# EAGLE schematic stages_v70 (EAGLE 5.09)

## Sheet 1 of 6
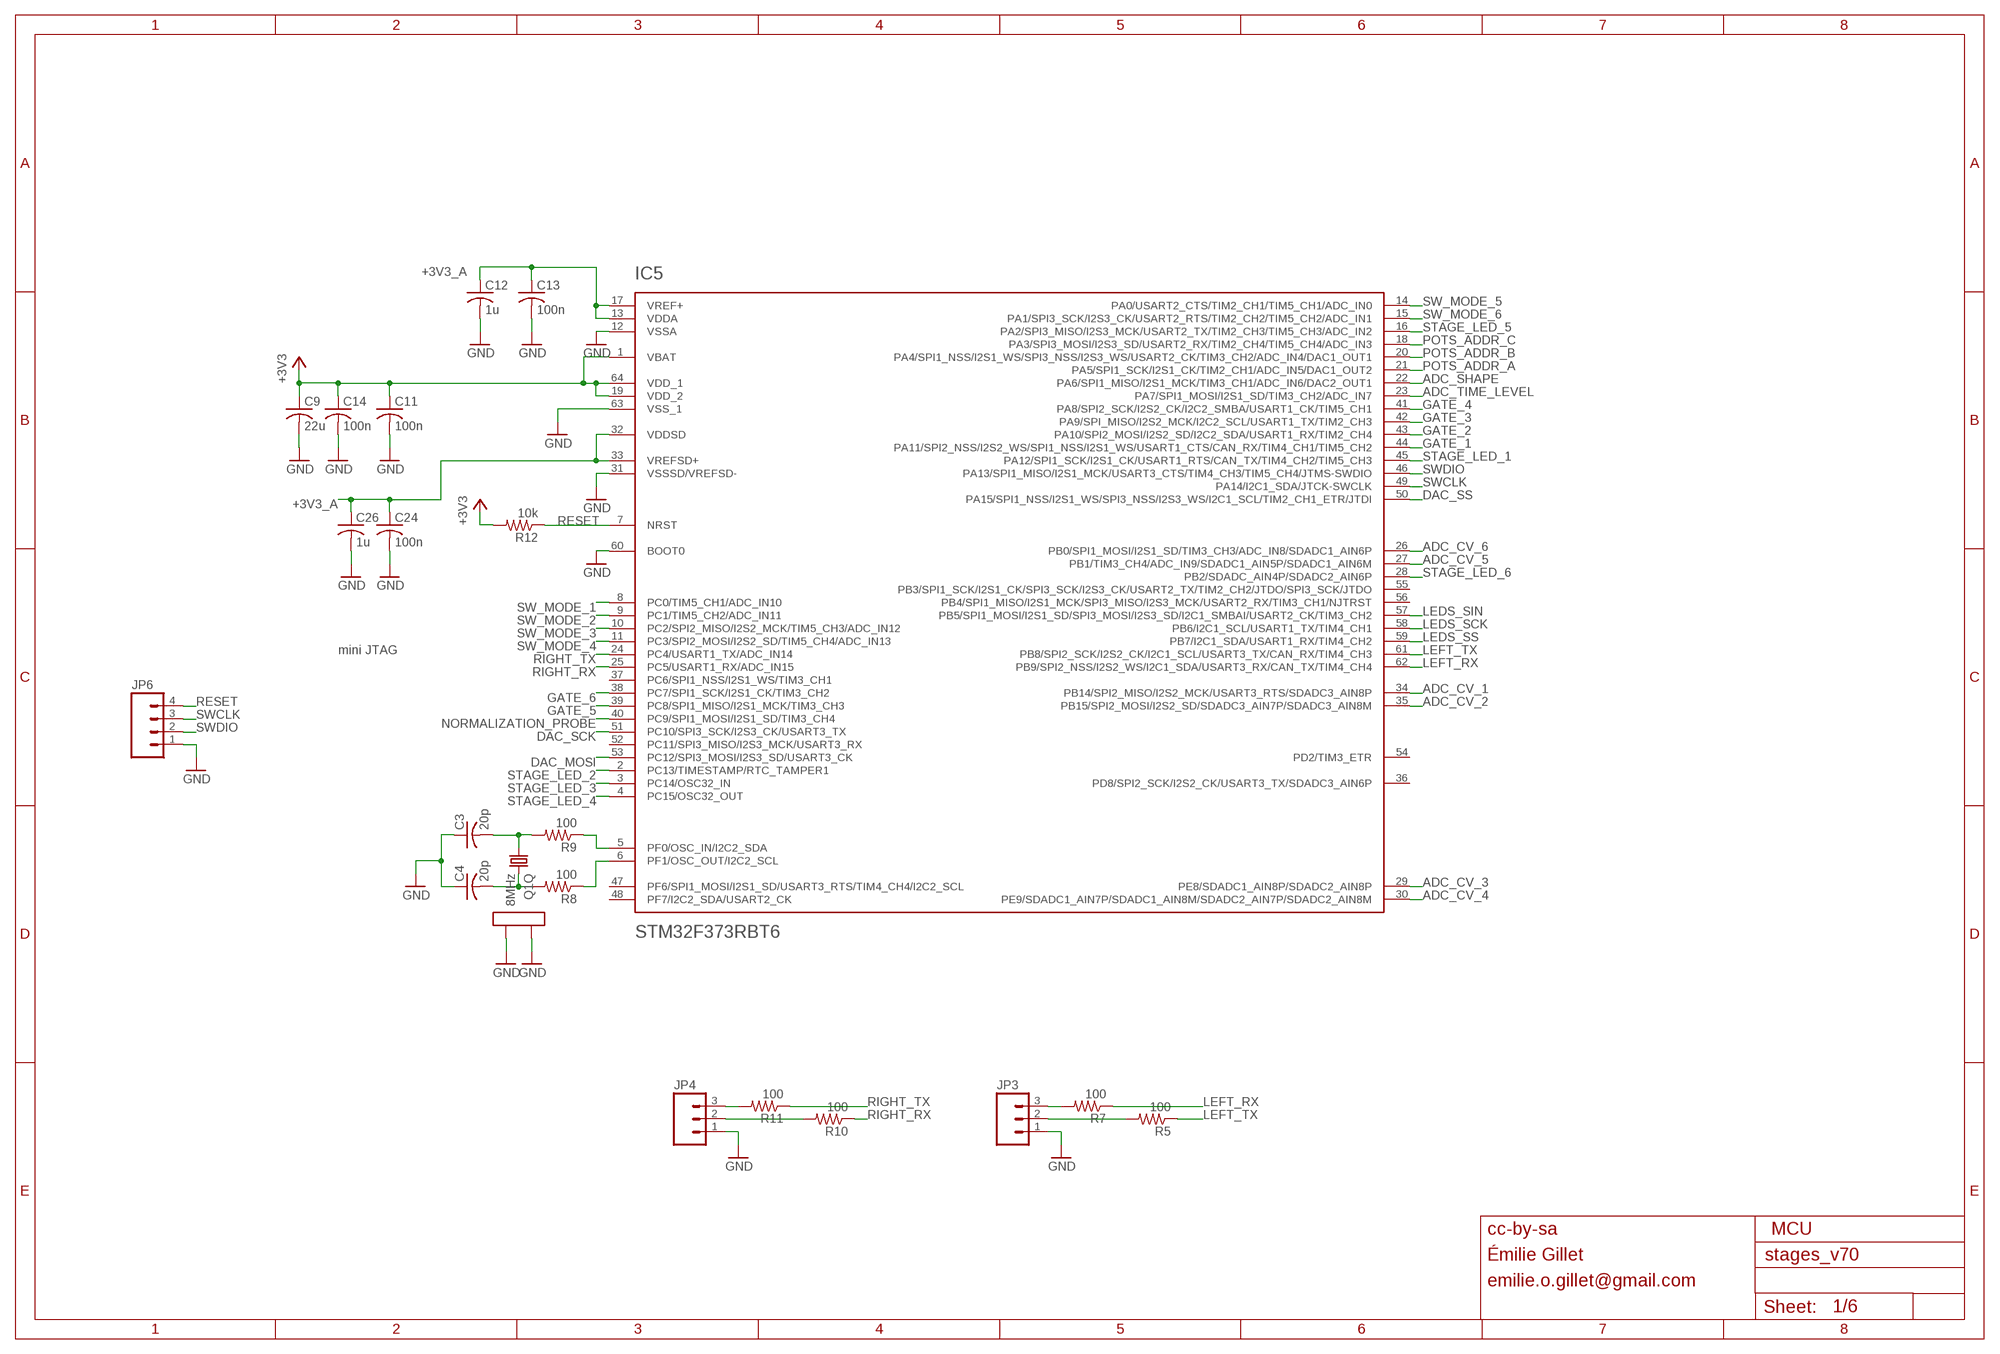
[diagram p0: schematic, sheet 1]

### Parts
C3  20p  C-USC0402  [C0402]
C4  20p  C-USC0402  [C0402]
C9  22u  C-USC1206  [C1206]
C11  100n  C-USC0402  [C0402]
C12  1u  C-USC0402  [C0402]
C13  100n  C-USC0402  [C0402]
C14  100n  C-USC0402  [C0402]
C24  100n  C-USC0402  [C0402]
C26  1u  C-USC0402  [C0402]
IC5  STM32F373RBT6  STM32F373R  [TQFP-10X10-64]
JP3  M03PTH  [1X03]
JP4  M03PTH  [1X03]
JP6  M04PTH  [1X04]
Q1  8MHz  CRYSTAL  [CTS406]
R5  100  R-US_R0402  [R0402]
R7  100  R-US_R0402  [R0402]
R8  100  R-US_R0402  [R0402]
R9  100  R-US_R0402  [R0402]
R10  100  R-US_R0402  [R0402]
R11  100  R-US_R0402  [R0402]
R12  10k  R-US_R0402  [R0402]

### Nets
+3V3: C9.1 C11.1 C14.1 IC5.1(VBAT) IC5.19(VDD_2) IC5.64(VDD_1) R12.2 ; also sheet 2,4,6
+3V3_A: C12.1 C13.1 C24.1 C26.1 IC5.13(VDDA) IC5.17(VREF+) IC5.32(VDDSD) IC5.33(VREFSD+) ; also sheet 2,3,5,6
ADC_CV_1: IC5.34(PB14/SPI2_MISO/I2S2_MCK/USART3_RTS/SDADC3_AIN8P) ; also sheet 3
ADC_CV_2: IC5.35(PB15/SPI2_MOSI/I2S2_SD/SDADC3_AIN7P/SDADC3_AIN8M) ; also sheet 3
ADC_CV_3: IC5.29(PE8/SDADC1_AIN8P/SDADC2_AIN8P) ; also sheet 3
ADC_CV_4: IC5.30(PE9/SDADC1_AIN7P/SDADC1_AIN8M/SDADC2_AIN7P/SDADC2_AIN8M) ; also sheet 3
ADC_CV_5: IC5.27(PB1/TIM3_CH4/ADC_IN9/SDADC1_AIN5P/SDADC1_AIN6M) ; also sheet 3
ADC_CV_6: IC5.26(PB0/SPI1_MOSI/I2S1_SD/TIM3_CH3/ADC_IN8/SDADC1_AIN6P) ; also sheet 3
ADC_SHAPE: IC5.22(PA6/SPI1_MISO/I2S1_MCK/TIM3_CH1/ADC_IN6/DAC2_OUT1) ; also sheet 2
ADC_TIME_LEVEL: IC5.23(PA7/SPI1_MOSI/I2S1_SD/TIM3_CH2/ADC_IN7) ; also sheet 2
DAC_MOSI: IC5.53(PC12/SPI3_MOSI/I2S3_SD/USART3_CK) ; also sheet 5
DAC_SCK: IC5.51(PC10/SPI3_SCK/I2S3_CK/USART3_TX) ; also sheet 5
DAC_SS: IC5.50(PA15/SPI1_NSS/I2S1_WS/SPI3_NSS/I2S3_WS/I2C1_SCL/TIM2_CH1_ETR/JTDI) ; also sheet 5
GATE_1: IC5.44(PA11/SPI2_NSS/I2S2_WS/SPI1_NSS/I2S1_WS/USART1_CTS/CAN_RX/TIM4_CH1/TIM5_CH2) ; also sheet 4
GATE_2: IC5.43(PA10/SPI2_MOSI/I2S2_SD/I2C2_SDA/USART1_RX/TIM2_CH4) ; also sheet 4
GATE_3: IC5.42(PA9/SPI_MISO/I2S2_MCK/I2C2_SCL/USART1_TX/TIM2_CH3) ; also sheet 4
GATE_4: IC5.41(PA8/SPI2_SCK/I2S2_CK/I2C2_SMBA/USART1_CK/TIM5_CH1) ; also sheet 4
GATE_5: IC5.39(PC8/SPI1_MISO/I2S1_MCK/TIM3_CH3) ; also sheet 4
GATE_6: IC5.38(PC7/SPI1_SCK/I2S1_CK/TIM3_CH2) ; also sheet 4
GND: C3.1 C4.1 C9.2 C11.2 C12.2 C13.2 C14.2 C24.2 C26.2 IC5.12(VSSA) IC5.31(VSSSD/VREFSD-) IC5.60(BOOT0) IC5.63(VSS_1) JP3.1 JP4.1 JP6.1 Q1.2(LID1) Q1.4(LID2) ; also sheet 2,3,4,5,6
LEDS_SCK: IC5.58(PB6/I2C1_SCL/USART1_TX/TIM4_CH1) ; also sheet 2
LEDS_SIN: IC5.57(PB5/SPI1_MOSI/I2S1_SD/SPI3_MOSI/I2S3_SD/I2C1_SMBAI/USART2_CK/TIM3_CH2) ; also sheet 2
LEDS_SS: IC5.59(PB7/I2C1_SDA/USART1_RX/TIM4_CH2) ; also sheet 2
LEFT_RX: IC5.62(PB9/SPI2_NSS/I2S2_WS/I2C1_SDA/USART3_RX/CAN_TX/TIM4_CH4) R7.1
LEFT_RX_R: JP3.3 R7.2
LEFT_TX: IC5.61(PB8/SPI2_SCK/I2S2_CK/I2C1_SCL/USART3_TX/CAN_RX/TIM4_CH3) R5.1
LEFT_TX_R: JP3.2 R5.2
N$7: C3.2 Q1.1 R9.2
N$8: C4.2 Q1.3 R8.2
N$15: IC5.5(PF0/OSC_IN/I2C2_SDA) R9.1
N$29: IC5.6(PF1/OSC_OUT/I2C2_SCL) R8.1
NORMALIZATION_PROBE: IC5.40(PC9/SPI1_MOSI/I2S1_SD/TIM3_CH4) ; also sheet 4
POTS_ADDR_A: IC5.21(PA5/SPI1_SCK/I2S1_CK/TIM2_CH1/ADC_IN5/DAC1_OUT2) ; also sheet 2
POTS_ADDR_B: IC5.20(PA4/SPI1_NSS/I2S1_WS/SPI3_NSS/I2S3_WS/USART2_CK/TIM3_CH2/ADC_IN4/DAC1_OUT1) ; also sheet 2
POTS_ADDR_C: IC5.18(PA3/SPI3_MOSI/I2S3_SD/USART2_RX/TIM2_CH4/TIM5_CH4/ADC_IN3) ; also sheet 2
RESET: IC5.7(NRST) JP6.4 R12.1
RIGHT_RX: IC5.25(PC5/USART1_RX/ADC_IN15) R10.1
RIGHT_RX_R: JP4.2 R10.2
RIGHT_TX: IC5.24(PC4/USART1_TX/ADC_IN14) R11.1
RIGHT_TX_R: JP4.3 R11.2
STAGE_LED_1: IC5.45(PA12/SPI1_SCK/I2S1_CK/USART1_RTS/CAN_TX/TIM4_CH2/TIM5_CH3) ; also sheet 2
STAGE_LED_2: IC5.2(PC13/TIMESTAMP/RTC_TAMPER1) ; also sheet 2
STAGE_LED_3: IC5.3(PC14/OSC32_IN) ; also sheet 2
STAGE_LED_4: IC5.4(PC15/OSC32_OUT) ; also sheet 2
STAGE_LED_5: IC5.16(PA2/SPI3_MISO/I2S3_MCK/USART2_TX/TIM2_CH3/TIM5_CH3/ADC_IN2) ; also sheet 2
STAGE_LED_6: IC5.28(PB2/SDADC_AIN4P/SDADC2_AIN6P) ; also sheet 2
SW_MODE_1: IC5.8(PC0/TIM5_CH1/ADC_IN10) ; also sheet 2
SW_MODE_2: IC5.9(PC1/TIM5_CH2/ADC_IN11) ; also sheet 2
SW_MODE_3: IC5.10(PC2/SPI2_MISO/I2S2_MCK/TIM5_CH3/ADC_IN12) ; also sheet 2
SW_MODE_4: IC5.11(PC3/SPI2_MOSI/I2S2_SD/TIM5_CH4/ADC_IN13) ; also sheet 2
SW_MODE_5: IC5.14(PA0/USART2_CTS/TIM2_CH1/TIM5_CH1/ADC_IN0) ; also sheet 2
SW_MODE_6: IC5.15(PA1/SPI3_SCK/I2S3_CK/USART2_RTS/TIM2_CH2/TIM5_CH2/ADC_IN1) ; also sheet 2
SWCLK: IC5.49(PA14/I2C1_SDA/JTCK-SWCLK) JP6.3
SWDIO: IC5.46(PA13/SPI1_MISO/I2S1_MCK/USART3_CTS/TIM4_CH3/TIM5_CH4/JTMS-SWDIO) JP6.2
Unconnected: IC5.36(PD8/SPI2_SCK/I2S2_CK/USART3_TX/SDADC3_AIN6P) IC5.37(PC6/SPI1_NSS/I2S1_WS/TIM3_CH1) IC5.47(PF6/SPI1_MOSI/I2S1_SD/USART3_RTS/TIM4_CH4/I2C2_SCL) IC5.48(PF7/I2C2_SDA/USART2_CK) IC5.52(PC11/SPI3_MISO/I2S3_MCK/USART3_RX) IC5.54(PD2/TIM3_ETR) IC5.55(PB3/SPI1_SCK/I2S1_CK/SPI3_SCK/I2S3_CK/USART2_TX/TIM2_CH2/JTDO/SPI3_SCK/JTDO) IC5.56(PB4/SPI1_MISO/I2S1_MCK/SPI3_MISO/I2S3_MCK/USART2_RX/TIM3_CH1/NJTRST)

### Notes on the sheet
- mini JTAG
- cc-by-sa | MCU
- Émilie Gillet
- emilie.o.gillet@gmail.com

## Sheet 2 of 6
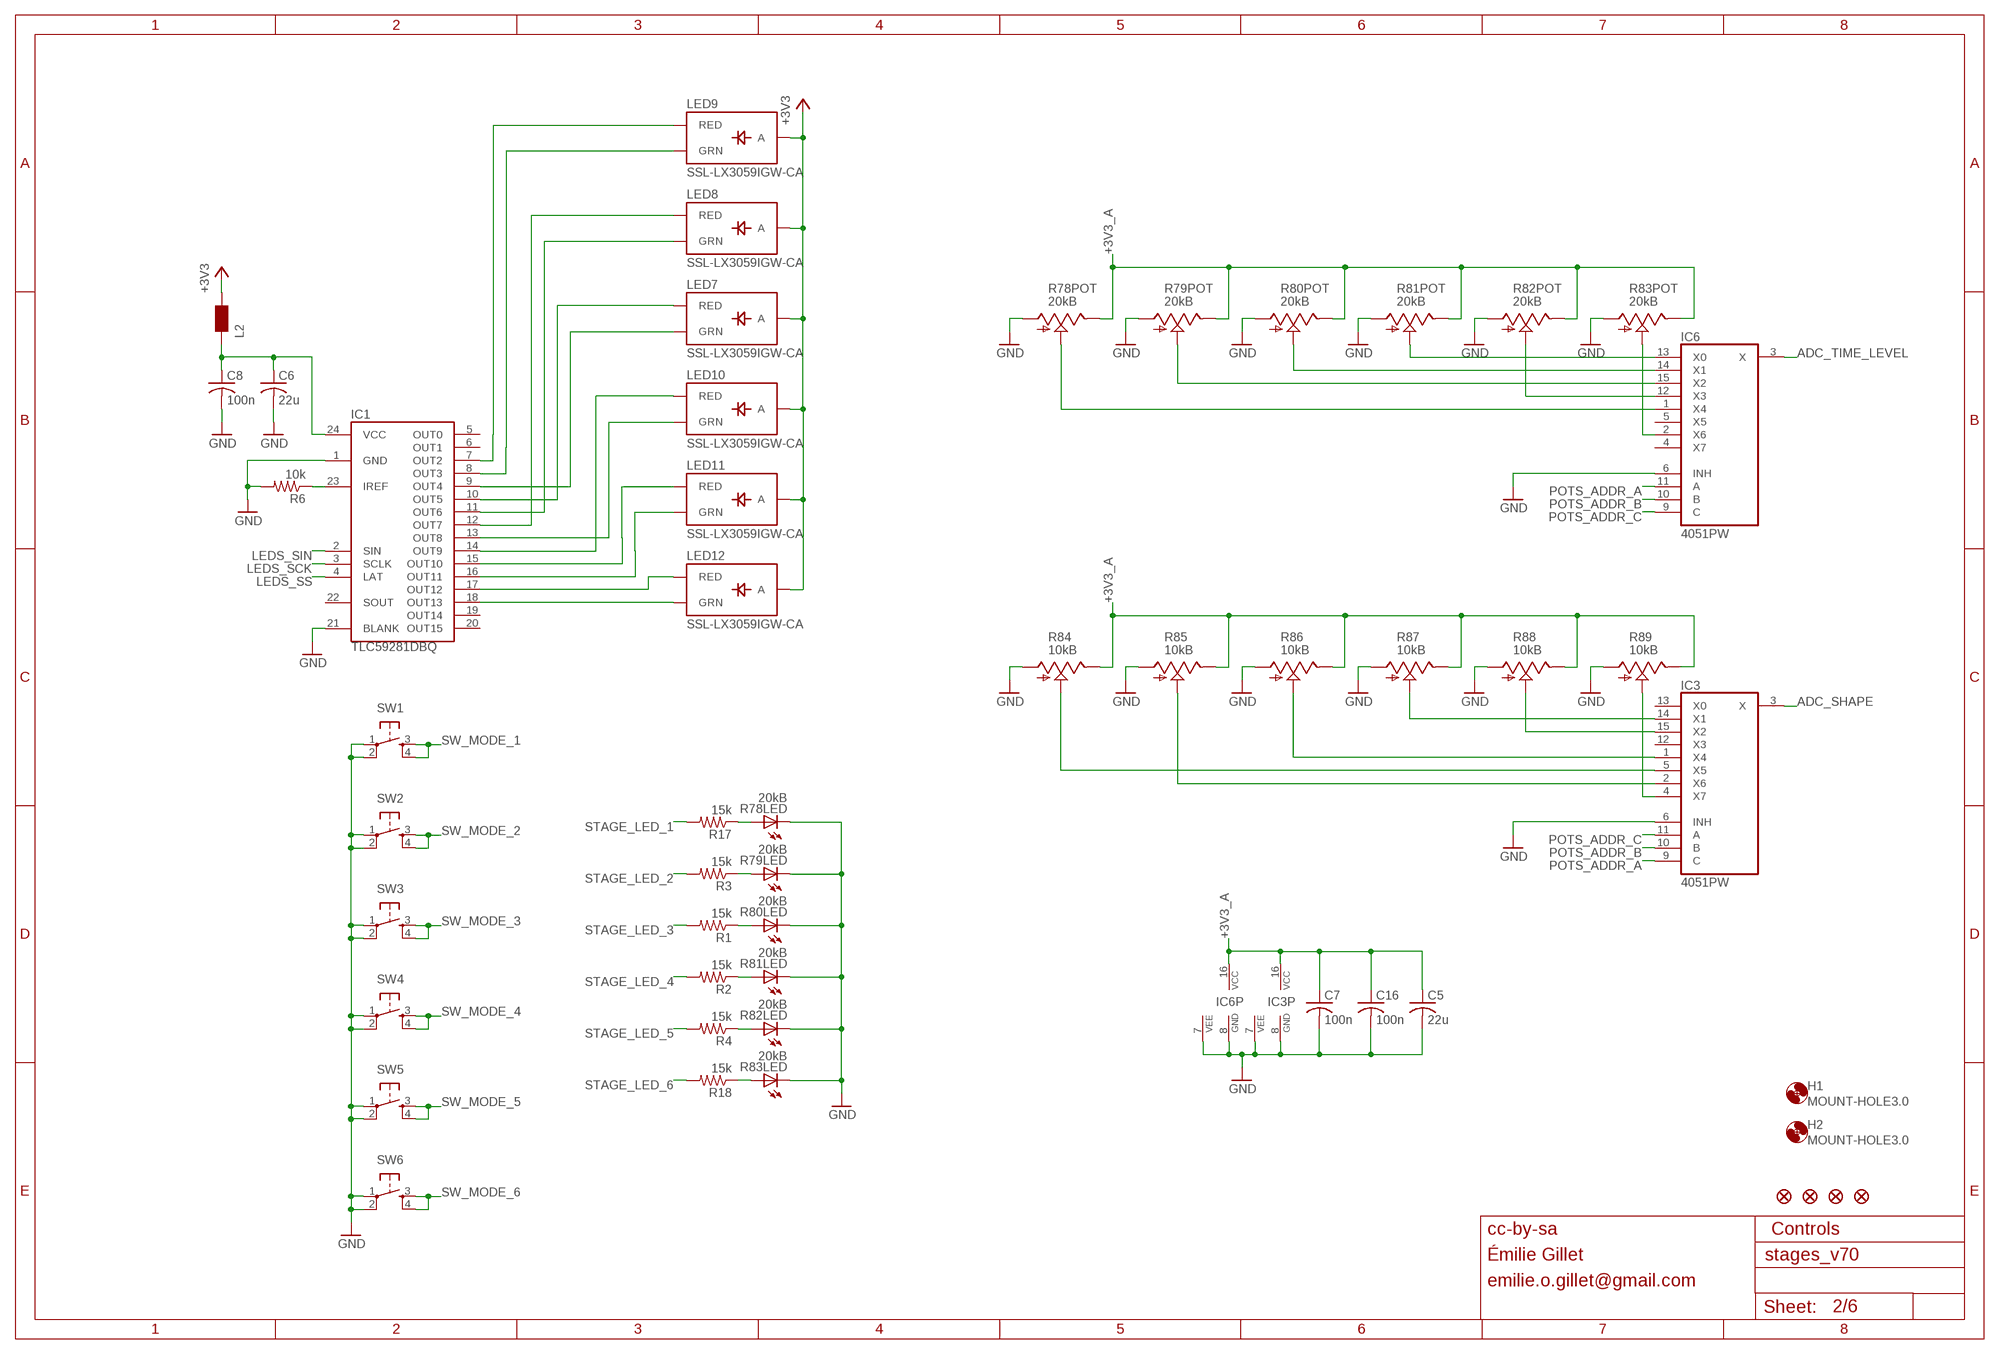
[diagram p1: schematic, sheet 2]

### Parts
C5  22u  C-USC1206  [C1206]
C6  22u  C-USC1206  [C1206]
C7  100n  C-USC0402  [C0402]
C8  100n  C-USC0402  [C0402]
C16  100n  C-USC0402  [C0402]
H1  MOUNT-HOLE3.0  [3,0]
H2  MOUNT-HOLE3.0  [3,0]
IC1  TLC59281DBQ  [TSSOP24_0635]
IC3  4051PW  [TSSOP16_065]
IC6  4051PW  [TSSOP16_065]
JP1  FIDUCIAL1X2  [FIDUCIAL-1X2]
JP2  FIDUCIAL1X2  [FIDUCIAL-1X2]
JP7  FIDUCIAL1X2  [FIDUCIAL-1X2]
JP8  FIDUCIAL1X2  [FIDUCIAL-1X2]
L2  WE-CBF_0603  [0603]
LED7  SSL-LX3059IGW-CA  LED-BICOLOR-THROUGHHOLE-CA  [LED-BICOLOR-THROUGHHOLE-LUMEX]
LED8  SSL-LX3059IGW-CA  LED-BICOLOR-THROUGHHOLE-CA  [LED-BICOLOR-THROUGHHOLE-LUMEX]
LED9  SSL-LX3059IGW-CA  LED-BICOLOR-THROUGHHOLE-CA  [LED-BICOLOR-THROUGHHOLE-LUMEX]
LED10  SSL-LX3059IGW-CA  LED-BICOLOR-THROUGHHOLE-CA  [LED-BICOLOR-THROUGHHOLE-LUMEX]
LED11  SSL-LX3059IGW-CA  LED-BICOLOR-THROUGHHOLE-CA  [LED-BICOLOR-THROUGHHOLE-LUMEX]
LED12  SSL-LX3059IGW-CA  LED-BICOLOR-THROUGHHOLE-CA  [LED-BICOLOR-THROUGHHOLE-LUMEX]
R1  15k  R-US_R0402  [R0402]
R2  15k  R-US_R0402  [R0402]
R3  15k  R-US_R0402  [R0402]
R4  15k  R-US_R0402  [R0402]
R6  10k  R-US_R0402  [R0402]
R17  15k  R-US_R0402  [R0402]
R18  15k  R-US_R0402  [R0402]
R78  20kB  BOURNS_SLIDER  [BOURNS_SLIDER]
R79  20kB  BOURNS_SLIDER  [BOURNS_SLIDER]
R80  20kB  BOURNS_SLIDER  [BOURNS_SLIDER]
R81  20kB  BOURNS_SLIDER  [BOURNS_SLIDER]
R82  20kB  BOURNS_SLIDER  [BOURNS_SLIDER]
R83  20kB  BOURNS_SLIDER  [BOURNS_SLIDER]
R84  10kB  POT_USVERTICAL_NARROW  [ALPS_POT_NARROW]
R85  10kB  POT_USVERTICAL_NARROW  [ALPS_POT_NARROW]
R86  10kB  POT_USVERTICAL_NARROW  [ALPS_POT_NARROW]
R87  10kB  POT_USVERTICAL_NARROW  [ALPS_POT_NARROW]
R88  10kB  POT_USVERTICAL_NARROW  [ALPS_POT_NARROW]
R89  10kB  POT_USVERTICAL_NARROW  [ALPS_POT_NARROW]
SW1  TAC_SWITCHPTH  [TACTILE-PTH]
SW2  TAC_SWITCHPTH  [TACTILE-PTH]
SW3  TAC_SWITCHPTH  [TACTILE-PTH]
SW4  TAC_SWITCHPTH  [TACTILE-PTH]
SW5  TAC_SWITCHPTH  [TACTILE-PTH]
SW6  TAC_SWITCHPTH  [TACTILE-PTH]

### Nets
+3V3: L2.2 LED7.A LED8.A LED9.A LED10.A LED11.A LED12.A ; also sheet 1,4,6
+3V3_A: C5.1 C7.1 C16.1 IC3.16(VCC) IC6.16(VCC) R78.3(POT:E) R79.3(POT:E) R80.3(POT:E) R81.3(POT:E) R82.3(POT:E) R83.3(POT:E) R84.P$1(E) R85.P$1(E) R86.P$1(E) R87.P$1(E) R88.P$1(E) R89.P$1(E) ; also sheet 1,3,5,6
ADC_SHAPE: IC3.3(X) ; also sheet 1
ADC_TIME_LEVEL: IC6.3(X) ; also sheet 1
GND: C5.2 C6.2 C7.2 C8.2 C16.2 IC1.1(GND) IC1.21(BLANK) IC3.6(INH) IC3.7(VEE) IC3.8(GND) IC6.6(INH) IC6.7(VEE) IC6.8(GND) R6.2 R78.1(POT:A) R78.E(LED:C) R79.1(POT:A) R79.E(LED:C) R80.1(POT:A) R80.E(LED:C) R81.1(POT:A) R81.E(LED:C) R82.1(POT:A) R82.E(LED:C) R83.1(POT:A) R83.E(LED:C) R84.P$3(A) R85.P$3(A) R86.P$3(A) R87.P$3(A) R88.P$3(A) R89.P$3(A) SW1.1 SW1.2 SW2.1 SW2.2 SW3.1 SW3.2 SW4.1 SW4.2 SW5.1 SW5.2 SW6.1 SW6.2 ; also sheet 1,3,4,5,6
LEDS_SCK: IC1.3(SCLK) ; also sheet 1
LEDS_SIN: IC1.2(SIN) ; also sheet 1
LEDS_SS: IC1.4(LAT) ; also sheet 1
N$2: IC1.10(OUT5) LED7.RED_C(RED)
N$3: IC1.18(OUT13) LED12.GREEN_C(GRN)
N$4: IC1.12(OUT7) LED8.RED_C(RED)
N$6: IC1.7(OUT2) LED9.RED_C(RED)
N$9: IC1.8(OUT3) LED9.GREEN_C(GRN)
N$10: IC1.13(OUT8) LED10.GREEN_C(GRN)
N$12: IC1.15(OUT10) LED11.RED_C(RED)
N$13: R17.1 R78.B(LED:A)
N$14: IC1.16(OUT11) LED11.GREEN_C(GRN)
N$16: IC1.17(OUT12) LED12.RED_C(RED)
N$22: IC1.11(OUT6) LED8.GREEN_C(GRN)
N$31: C6.1 C8.1 IC1.24(VCC) L2.1
N$43: IC1.14(OUT9) LED10.RED_C(RED)
N$48: IC6.1(X4) R78.2(POT:S)
N$49: R18.1 R83.B(LED:A)
N$51: IC6.2(X6) R83.2(POT:S)
N$53: IC6.12(X3) R82.2(POT:S)
N$54: IC6.13(X0) R81.2(POT:S)
N$55: IC6.14(X1) R80.2(POT:S)
N$56: IC6.15(X2) R79.2(POT:S)
N$58: IC3.2(X6) R85.P$2(S)
N$59: IC3.4(X7) R89.P$2(S)
N$60: IC3.1(X4) R86.P$2(S)
N$61: IC3.14(X1) R87.P$2(S)
N$62: IC3.15(X2) R88.P$2(S)
N$63: IC3.5(X5) R84.P$2(S)
N$64: R4.1 R82.B(LED:A)
N$68: IC1.23(IREF) R6.1
N$100: R2.1 R81.B(LED:A)
N$101: IC1.9(OUT4) LED7.GREEN_C(GRN)
N$102: R1.1 R80.B(LED:A)
N$103: R3.1 R79.B(LED:A)
POTS_ADDR_A: IC3.9(C) IC6.11(A) ; also sheet 1
POTS_ADDR_B: IC3.10(B) IC6.10(B) ; also sheet 1
POTS_ADDR_C: IC3.11(A) IC6.9(C) ; also sheet 1
STAGE_LED_1: R17.2 ; also sheet 1
STAGE_LED_2: R3.2 ; also sheet 1
STAGE_LED_3: R1.2 ; also sheet 1
STAGE_LED_4: R2.2 ; also sheet 1
STAGE_LED_5: R4.2 ; also sheet 1
STAGE_LED_6: R18.2 ; also sheet 1
SW_MODE_1: SW1.3 SW1.4 ; also sheet 1
SW_MODE_2: SW2.3 SW2.4 ; also sheet 1
SW_MODE_3: SW3.3 SW3.4 ; also sheet 1
SW_MODE_4: SW4.3 SW4.4 ; also sheet 1
SW_MODE_5: SW5.3 SW5.4 ; also sheet 1
SW_MODE_6: SW6.3 SW6.4 ; also sheet 1
Unconnected: IC1.5(OUT0) IC1.6(OUT1) IC1.19(OUT14) IC1.20(OUT15) IC1.22(SOUT) IC3.12(X3) IC3.13(X0) IC6.4(X7) IC6.5(X5)

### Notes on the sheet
- cc-by-sa | Controls
- Émilie Gillet
- emilie.o.gillet@gmail.com

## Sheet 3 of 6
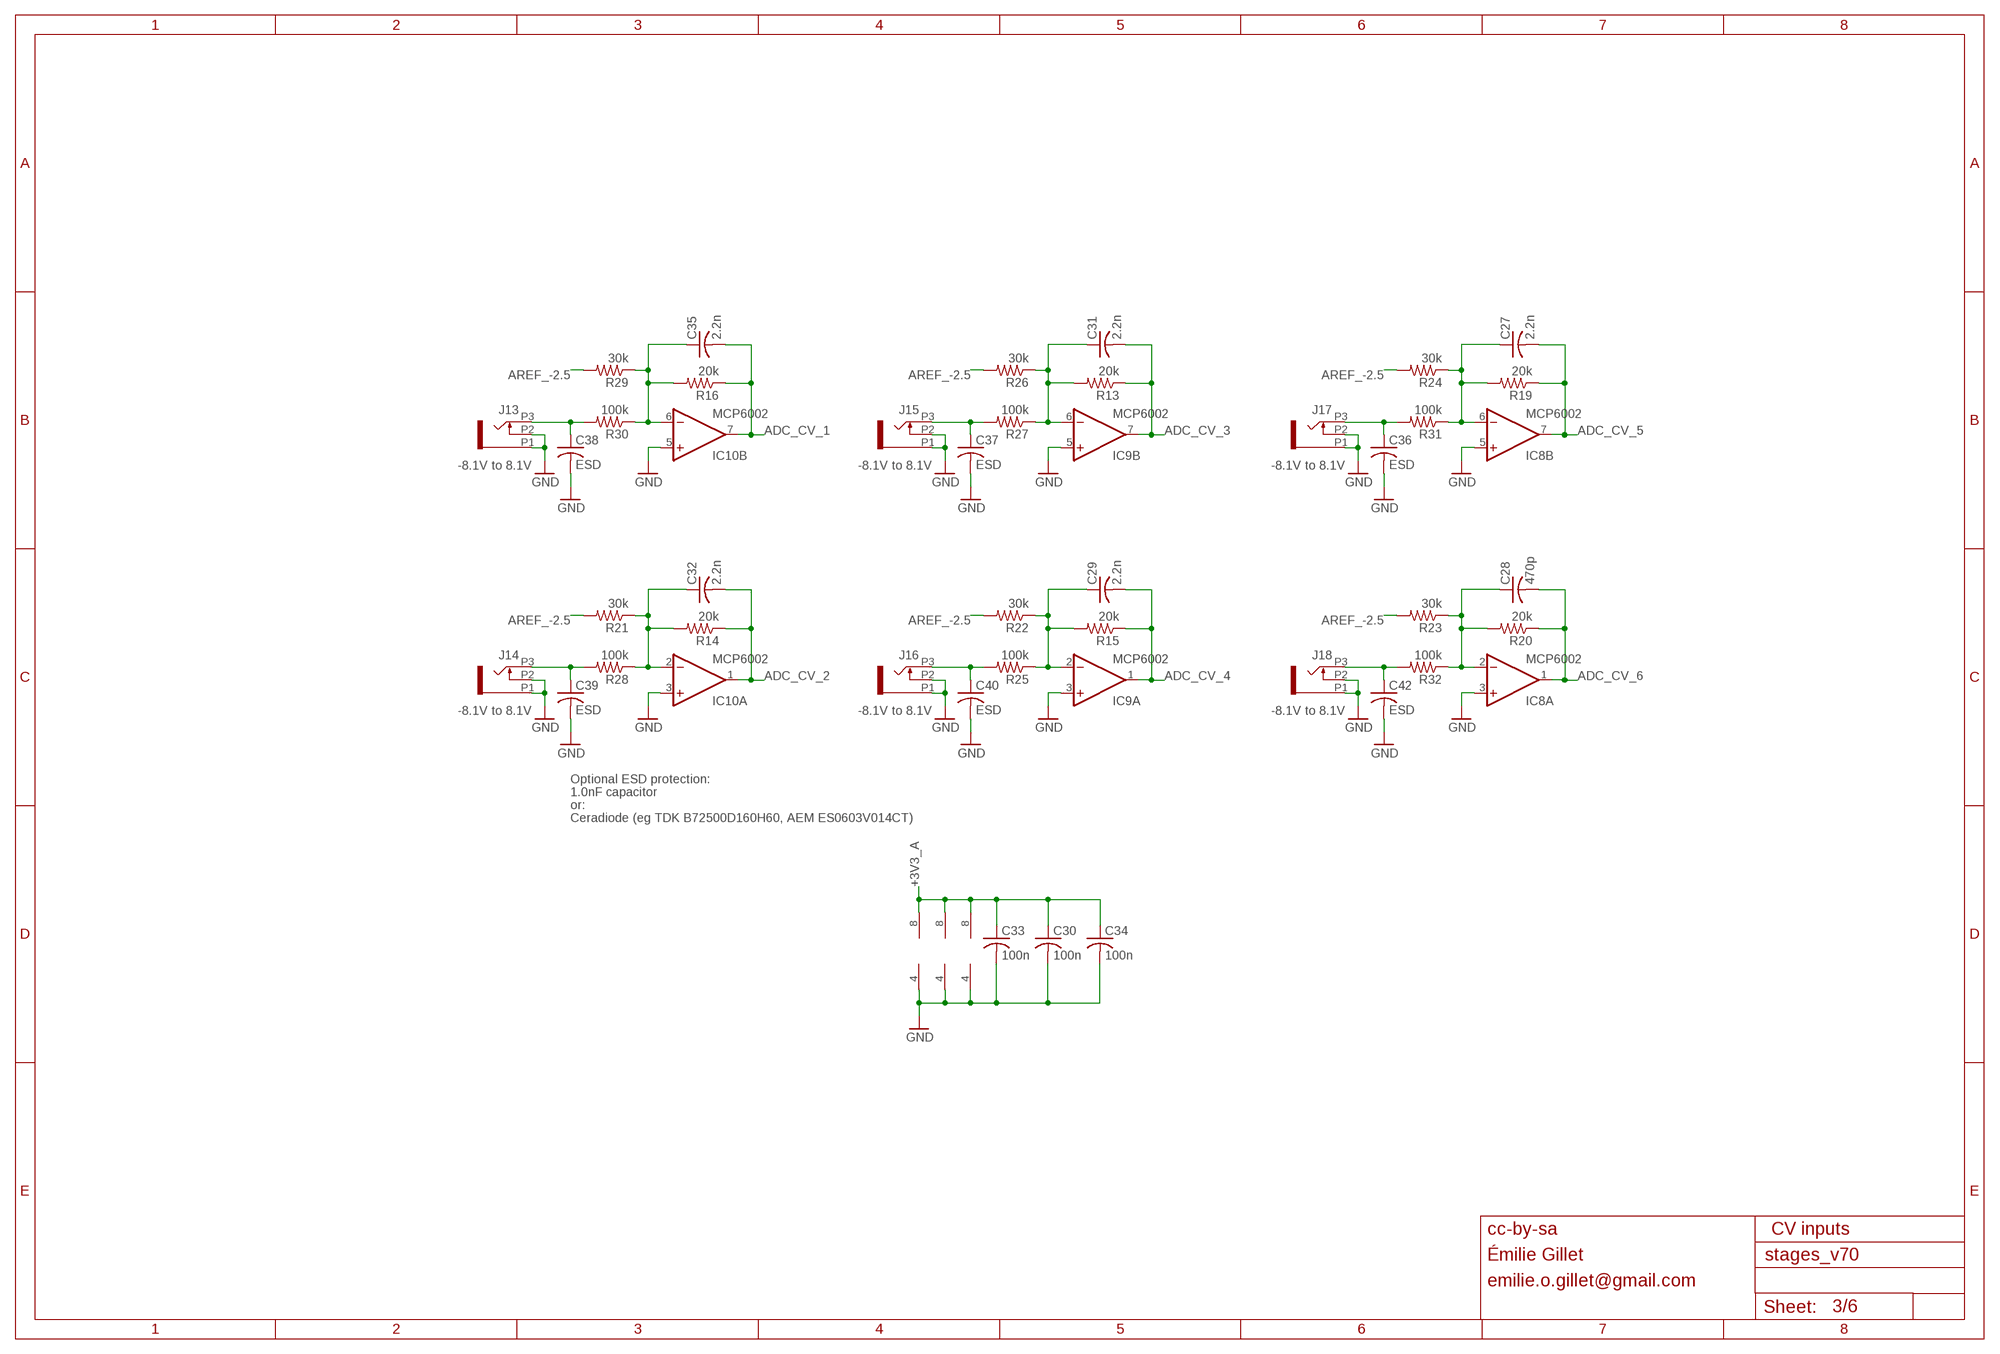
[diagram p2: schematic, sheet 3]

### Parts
C27  2.2n  C-USC0402  [C0402]
C28  470p  C-USC0402  [C0402]
C29  2.2n  C-USC0402  [C0402]
C30  100n  C-USC0402  [C0402]
C31  2.2n  C-USC0402  [C0402]
C32  2.2n  C-USC0402  [C0402]
C33  100n  C-USC0402  [C0402]
C34  100n  C-USC0402  [C0402]
C35  2.2n  C-USC0402  [C0402]
C36  ESD  C-USC0603  [C0603]
C37  ESD  C-USC0603  [C0603]
C38  ESD  C-USC0603  [C0603]
C39  ESD  C-USC0603  [C0603]
C40  ESD  C-USC0603  [C0603]
C42  ESD  C-USC0603  [C0603]
IC8  MCP6002  OPA1652DGK  [MSOP-8]
IC9  MCP6002  OPA1652DGK  [MSOP-8]
IC10  MCP6002  OPA1652DGK  [MSOP-8]
J13  PJ301_THONKICONN6  [WQP_PJ_301M6]
J14  PJ301_THONKICONN6  [WQP_PJ_301M6]
J15  PJ301_THONKICONN6  [WQP_PJ_301M6]
J16  PJ301_THONKICONN6  [WQP_PJ_301M6]
J17  PJ301_THONKICONN6  [WQP_PJ_301M6]
J18  PJ301_THONKICONN6  [WQP_PJ_301M6]
R13  20k  R-US_R0402  [R0402]
R14  20k  R-US_R0402  [R0402]
R15  20k  R-US_R0402  [R0402]
R16  20k  R-US_R0402  [R0402]
R19  20k  R-US_R0402  [R0402]
R20  20k  R-US_R0402  [R0402]
R21  30k  R-US_R0402  [R0402]
R22  30k  R-US_R0402  [R0402]
R23  30k  R-US_R0402  [R0402]
R24  30k  R-US_R0402  [R0402]
R25  100k  R-US_R0402  [R0402]
R26  30k  R-US_R0402  [R0402]
R27  100k  R-US_R0402  [R0402]
R28  100k  R-US_R0402  [R0402]
R29  30k  R-US_R0402  [R0402]
R30  100k  R-US_R0402  [R0402]
R31  100k  R-US_R0402  [R0402]
R32  100k  R-US_R0402  [R0402]

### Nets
+3V3_A: C30.1 C33.1 C34.1 IC8.8(P:V+) IC9.8(P:V+) IC10.8(P:V+) ; also sheet 1,2,5,6
ADC_CV_1: C35.2 IC10.7(B:OUT) R16.1 ; also sheet 1
ADC_CV_2: C32.2 IC10.1(A:OUT) R14.1 ; also sheet 1
ADC_CV_3: C31.2 IC9.7(B:OUT) R13.1 ; also sheet 1
ADC_CV_4: C29.2 IC9.1(A:OUT) R15.1 ; also sheet 1
ADC_CV_5: C27.2 IC8.7(B:OUT) R19.1 ; also sheet 1
ADC_CV_6: C28.2 IC8.1(A:OUT) R20.1 ; also sheet 1
AREF_-2.5: R21.2 R22.2 R23.2 R24.2 R26.2 R29.2 ; also sheet 6
GND: C30.2 C33.2 C34.2 C36.2 C37.2 C38.2 C39.2 C40.2 C42.2 IC8.3(A:+IN) IC8.4(P:V-) IC8.5(B:+IN) IC9.3(A:+IN) IC9.4(P:V-) IC9.5(B:+IN) IC10.3(A:+IN) IC10.4(P:V-) IC10.5(B:+IN) J13.P1 J13.P2 J14.P1 J14.P2 J15.P1 J15.P2 J16.P1 J16.P2 J17.P1 J17.P2 J18.P1 J18.P2 ; also sheet 1,2,4,5,6
MORPH_IN: C38.1 J13.P3 R30.2
MORPH_IN1: C39.1 J14.P3 R28.2
MORPH_IN2: C37.1 J15.P3 R27.2
MORPH_IN3: C40.1 J16.P3 R25.2
MORPH_IN4: C36.1 J17.P3 R31.2
MORPH_IN5: C42.1 J18.P3 R32.2
N$30: C35.1 IC10.6(B:-IN) R16.2 R29.1 R30.1
N$32: C32.1 IC10.2(A:-IN) R14.2 R21.1 R28.1
N$34: C31.1 IC9.6(B:-IN) R13.2 R26.1 R27.1
N$37: C29.1 IC9.2(A:-IN) R15.2 R22.1 R25.1
N$39: C27.1 IC8.6(B:-IN) R19.2 R24.1 R31.1
N$41: C28.1 IC8.2(A:-IN) R20.2 R23.1 R32.1

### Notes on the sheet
- -8.1V to 8.1V | -8.1V to 8.1V | -8.1V to 8.1V
- -8.1V to 8.1V | -8.1V to 8.1V | -8.1V to 8.1V
- Optional ESD protection:
- 1.0nF capacitor
- or:
- Ceradiode (eg TDK B72500D160H60, AEM ES0603V014CT)
- cc-by-sa | CV inputs
- Émilie Gillet
- emilie.o.gillet@gmail.com

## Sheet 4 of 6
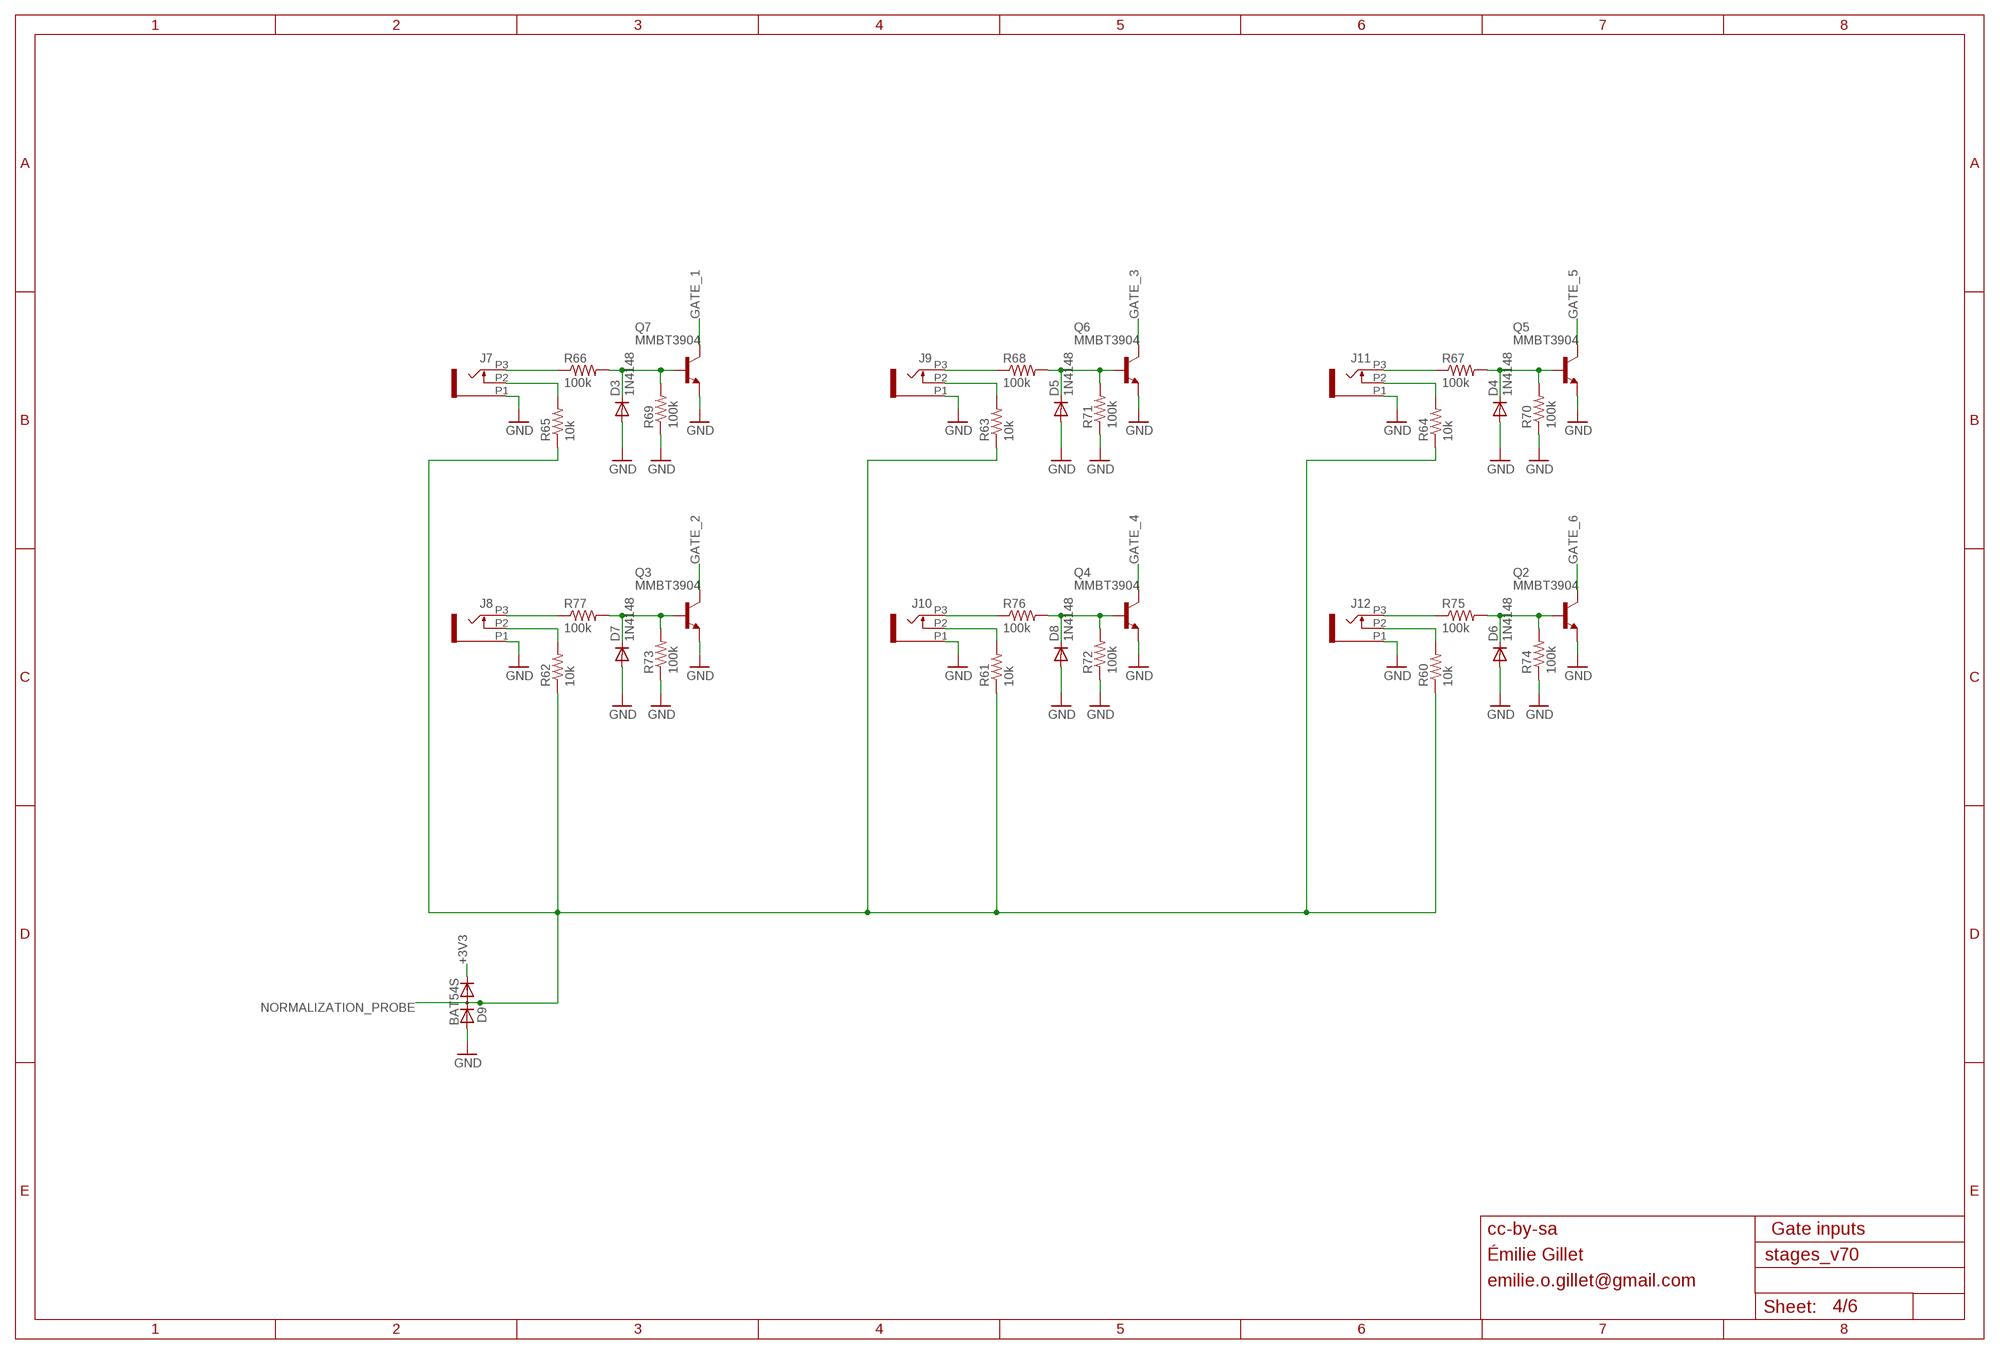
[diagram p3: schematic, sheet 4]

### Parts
D3  1N4148  DIODE-SOD523  [SOD523]
D4  1N4148  DIODE-SOD523  [SOD523]
D5  1N4148  DIODE-SOD523  [SOD523]
D6  1N4148  DIODE-SOD523  [SOD523]
D7  1N4148  DIODE-SOD523  [SOD523]
D8  1N4148  DIODE-SOD523  [SOD523]
D9  BAT54S  DIODE_2CACA-SOT23  [SOT23]
J7  PJ301_THONKICONN6  [WQP_PJ_301M6]
J8  PJ301_THONKICONN6  [WQP_PJ_301M6]
J9  PJ301_THONKICONN6  [WQP_PJ_301M6]
J10  PJ301_THONKICONN6  [WQP_PJ_301M6]
J11  PJ301_THONKICONN6  [WQP_PJ_301M6]
J12  PJ301_THONKICONN6  [WQP_PJ_301M6]
Q2  MMBT3904  MMBT3904LT1-NPN-SOT23-BEC  [SOT23-BEC]
Q3  MMBT3904  MMBT3904LT1-NPN-SOT23-BEC  [SOT23-BEC]
Q4  MMBT3904  MMBT3904LT1-NPN-SOT23-BEC  [SOT23-BEC]
Q5  MMBT3904  MMBT3904LT1-NPN-SOT23-BEC  [SOT23-BEC]
Q6  MMBT3904  MMBT3904LT1-NPN-SOT23-BEC  [SOT23-BEC]
Q7  MMBT3904  MMBT3904LT1-NPN-SOT23-BEC  [SOT23-BEC]
R60  10k  R-US_R0402  [R0402]
R61  10k  R-US_R0402  [R0402]
R62  10k  R-US_R0402  [R0402]
R63  10k  R-US_R0402  [R0402]
R64  10k  R-US_R0402  [R0402]
R65  10k  R-US_R0402  [R0402]
R66  100k  R-US_R0402  [R0402]
R67  100k  R-US_R0402  [R0402]
R68  100k  R-US_R0402  [R0402]
R69  100k  R-US_R0402  [R0402]
R70  100k  R-US_R0402  [R0402]
R71  100k  R-US_R0402  [R0402]
R72  100k  R-US_R0402  [R0402]
R73  100k  R-US_R0402  [R0402]
R74  100k  R-US_R0402  [R0402]
R75  100k  R-US_R0402  [R0402]
R76  100k  R-US_R0402  [R0402]
R77  100k  R-US_R0402  [R0402]

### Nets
+3V3: D9.2(C) ; also sheet 1,2,6
GATE_1: Q7.C ; also sheet 1
GATE_2: Q3.C ; also sheet 1
GATE_3: Q6.C ; also sheet 1
GATE_4: Q4.C ; also sheet 1
GATE_5: Q5.C ; also sheet 1
GATE_6: Q2.C ; also sheet 1
GND: D3.A D4.A D5.A D6.A D7.A D8.A D9.1(A) J7.P1 J8.P1 J9.P1 J10.P1 J11.P1 J12.P1 Q2.E Q3.E Q4.E Q5.E Q6.E Q7.E R69.1 R70.1 R71.1 R72.1 R73.1 R74.1 ; also sheet 1,2,3,5,6
N$1: J9.P3 R68.1
N$5: J10.P3 R76.1
N$17: J10.P2 R61.2
N$19: J9.P2 R63.2
N$20: D5.C Q6.B R68.2 R71.2
N$21: D8.C Q4.B R72.2 R76.2
N$23: J11.P3 R67.1
N$24: J12.P3 R75.1
N$25: J12.P2 R60.2
N$26: J11.P2 R64.2
N$27: D4.C Q5.B R67.2 R70.2
N$28: D6.C Q2.B R74.2 R75.2
N$36: J8.P3 R77.1
N$46: J8.P2 R62.2
N$47: J7.P2 R65.2
N$50: D3.C Q7.B R66.2 R69.2
N$52: D7.C Q3.B R73.2 R77.2
N$57: J7.P3 R66.1
NORMALIZATION_PROBE: D9.3(AC) R60.1 R61.1 R62.1 R63.1 R64.1 R65.1 ; also sheet 1

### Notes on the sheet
- cc-by-sa | Gate inputs
- Émilie Gillet
- emilie.o.gillet@gmail.com

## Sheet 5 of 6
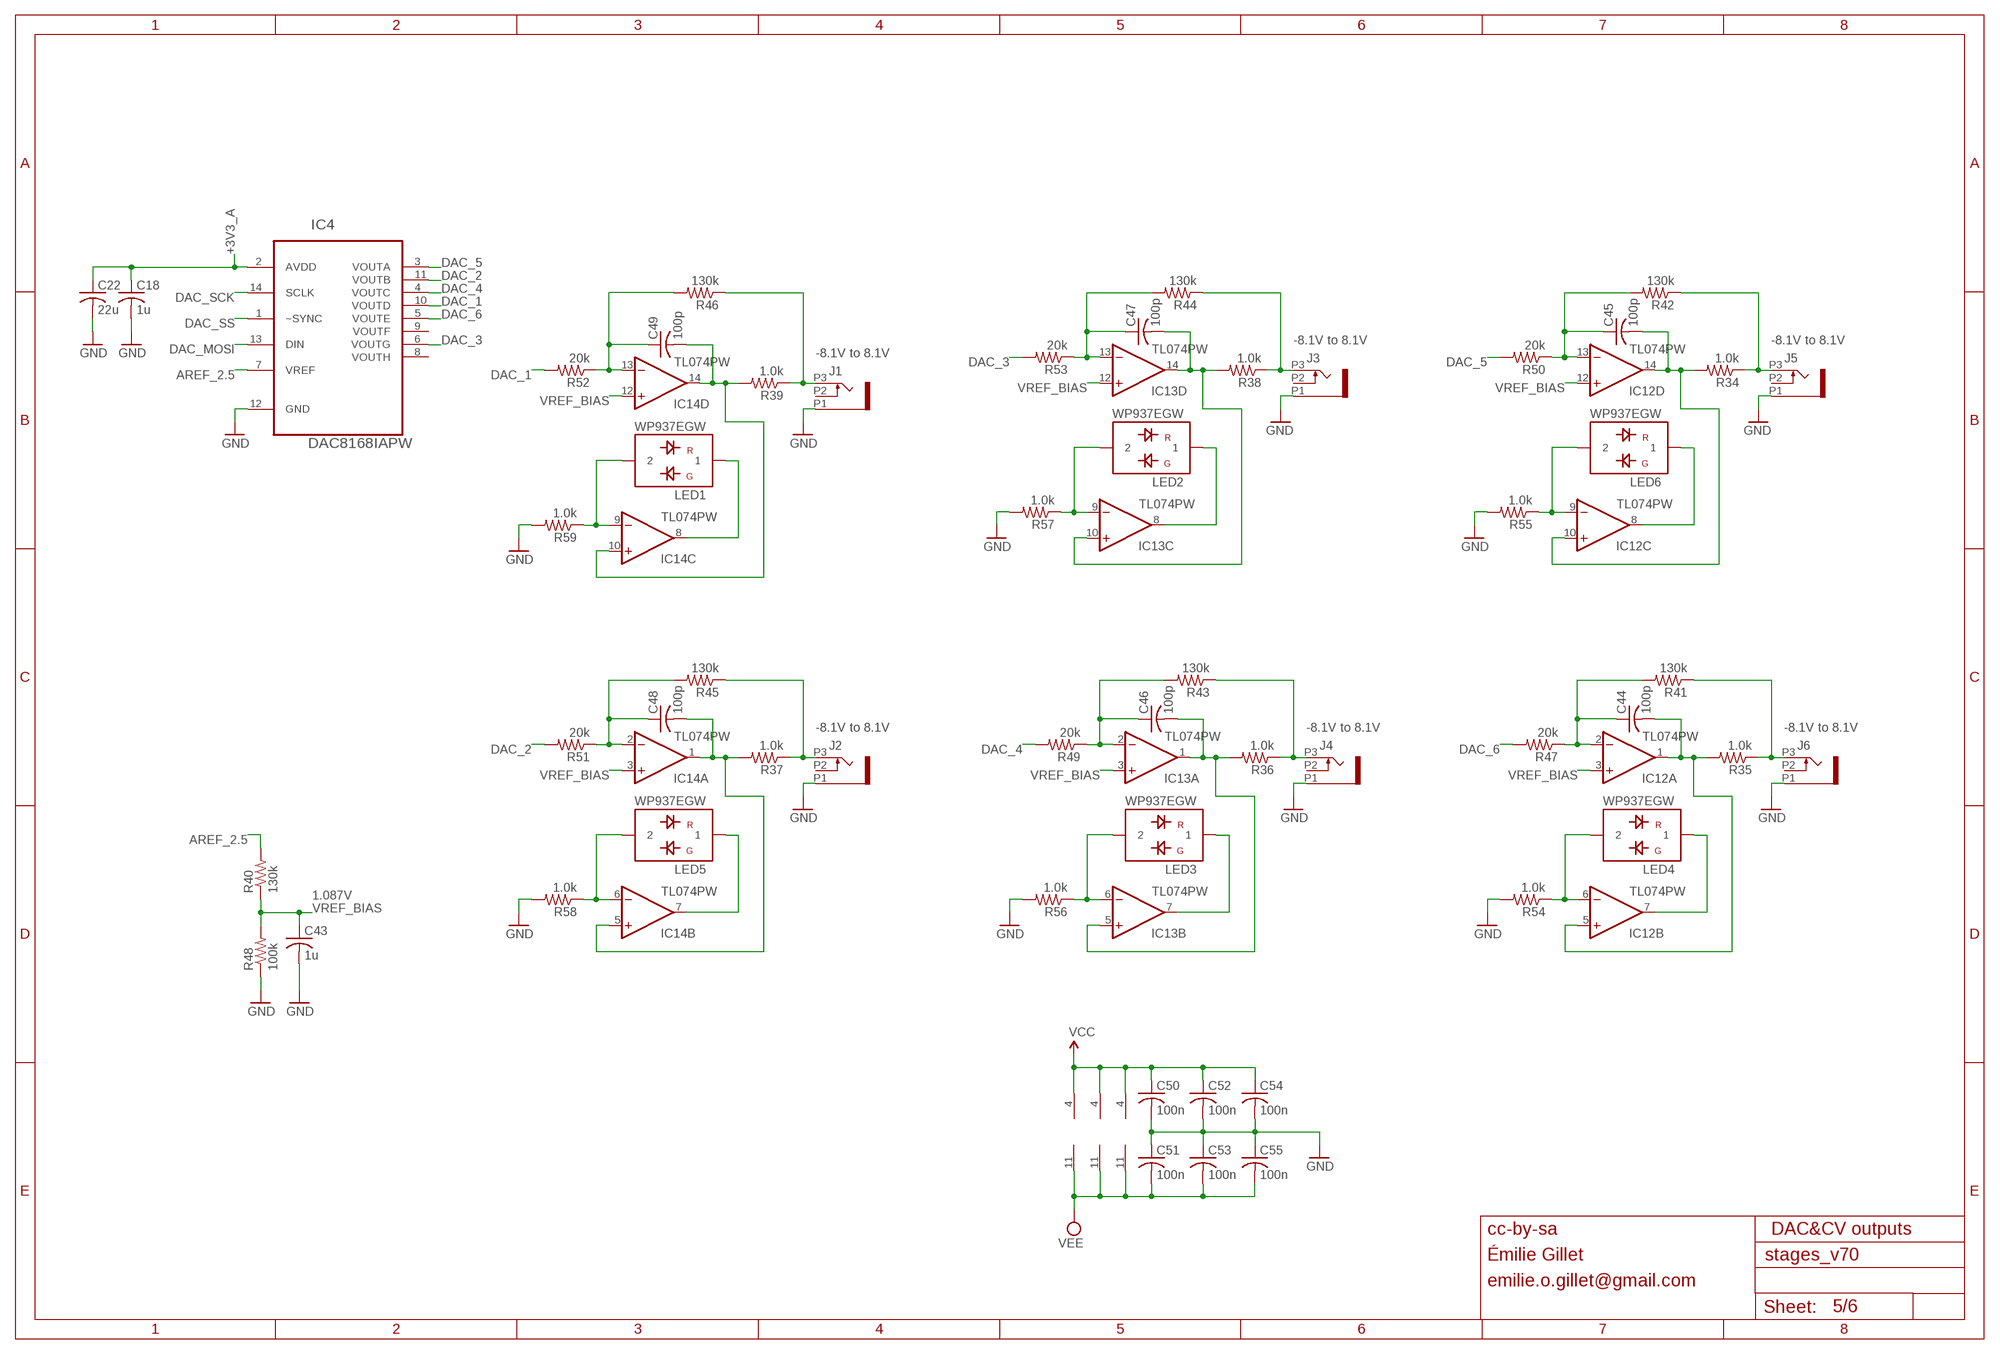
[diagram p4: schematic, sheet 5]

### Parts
C18  1u  C-USC0402  [C0402]
C22  22u  C-USC1206  [C1206]
C43  1u  C-USC0402  [C0402]
C44  100p  C-USC0402  [C0402]
C45  100p  C-USC0402  [C0402]
C46  100p  C-USC0402  [C0402]
C47  100p  C-USC0402  [C0402]
C48  100p  C-USC0402  [C0402]
C49  100p  C-USC0402  [C0402]
C50  100n  C-USC0402  [C0402]
C51  100n  C-USC0402  [C0402]
C52  100n  C-USC0402  [C0402]
C53  100n  C-USC0402  [C0402]
C54  100n  C-USC0402  [C0402]
C55  100n  C-USC0402  [C0402]
IC4  DAC8168IAPW  DAC8168PW  [RPDSOG14]
IC12  TL074PW  [TSSOP14_065]
IC13  TL074PW  [TSSOP14_065]
IC14  TL074PW  [TSSOP14_065]
J1  PJ301_THONKICONN6  [WQP_PJ_301M6]
J2  PJ301_THONKICONN6  [WQP_PJ_301M6]
J3  PJ301_THONKICONN6  [WQP_PJ_301M6]
J4  PJ301_THONKICONN6  [WQP_PJ_301M6]
J5  PJ301_THONKICONN6  [WQP_PJ_301M6]
J6  PJ301_THONKICONN6  [WQP_PJ_301M6]
LED1  WP937EGW  LED-BICOLOR-SHARED-THROUGHHOLE  [LED3MM]
LED2  WP937EGW  LED-BICOLOR-SHARED-THROUGHHOLE  [LED3MM]
LED3  WP937EGW  LED-BICOLOR-SHARED-THROUGHHOLE  [LED3MM]
LED4  WP937EGW  LED-BICOLOR-SHARED-THROUGHHOLE  [LED3MM]
LED5  WP937EGW  LED-BICOLOR-SHARED-THROUGHHOLE  [LED3MM]
LED6  WP937EGW  LED-BICOLOR-SHARED-THROUGHHOLE  [LED3MM]
R34  1.0k  R-US_R0603  [R0603]
R35  1.0k  R-US_R0603  [R0603]
R36  1.0k  R-US_R0603  [R0603]
R37  1.0k  R-US_R0603  [R0603]
R38  1.0k  R-US_R0603  [R0603]
R39  1.0k  R-US_R0603  [R0603]
R40  130k  R-US_R0402  [R0402]
R41  130k  R-US_R0402  [R0402]
R42  130k  R-US_R0402  [R0402]
R43  130k  R-US_R0402  [R0402]
R44  130k  R-US_R0402  [R0402]
R45  130k  R-US_R0402  [R0402]
R46  130k  R-US_R0402  [R0402]
R47  20k  R-US_R0402  [R0402]
R48  100k  R-US_R0402  [R0402]
R49  20k  R-US_R0402  [R0402]
R50  20k  R-US_R0402  [R0402]
R51  20k  R-US_R0402  [R0402]
R52  20k  R-US_R0402  [R0402]
R53  20k  R-US_R0402  [R0402]
R54  1.0k  R-US_R0402  [R0402]
R55  1.0k  R-US_R0402  [R0402]
R56  1.0k  R-US_R0402  [R0402]
R57  1.0k  R-US_R0402  [R0402]
R58  1.0k  R-US_R0402  [R0402]
R59  1.0k  R-US_R0402  [R0402]

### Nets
+3V3_A: C18.1 C22.1 IC4.2(AVDD) ; also sheet 1,2,3,6
AREF_2.5: IC4.7(VREF) R40.2
DAC_1: IC4.10(VOUTD) R52.2
DAC_2: IC4.11(VOUTB) R51.2
DAC_3: IC4.6(VOUTG) R53.2
DAC_4: IC4.4(VOUTC) R49.2
DAC_5: IC4.3(VOUTA) R50.2
DAC_6: IC4.5(VOUTE) R47.2
DAC_MOSI: IC4.13(DIN) ; also sheet 1
DAC_SCK: IC4.14(SCLK) ; also sheet 1
DAC_SS: IC4.1(~SYNC) ; also sheet 1
GND: C18.2 C22.2 C43.2 C50.2 C51.1 C52.2 C53.1 C54.2 C55.1 IC4.12(GND) J1.P1 J2.P1 J3.P1 J4.P1 J5.P1 J6.P1 R48.1 R54.2 R55.2 R56.2 R57.2 R58.2 R59.2 ; also sheet 1,2,3,4,6
N$65: C49.2 IC14.10(C:+IN) IC14.14(D:OUT) R39.2
N$66: J1.P3 R39.1 R46.1
N$67: J2.P3 R37.1 R45.1
N$69: J4.P3 R36.1 R43.1
N$70: C46.1 IC13.2(A:-IN) R43.2 R49.1
N$71: C48.1 IC14.2(A:-IN) R45.2 R51.1
N$72: C47.1 IC13.13(D:-IN) R44.2 R53.1
N$73: C49.1 IC14.13(D:-IN) R46.2 R52.1
N$74: J3.P3 R38.1 R44.1
N$75: IC14.9(C:-IN) LED1.2 R59.1
N$76: IC14.8(C:OUT) LED1.1
N$77: C47.2 IC13.10(C:+IN) IC13.14(D:OUT) R38.2
N$78: IC13.9(C:-IN) LED2.2 R57.1
N$79: IC13.8(C:OUT) LED2.1
N$80: C48.2 IC14.1(A:OUT) IC14.5(B:+IN) R37.2
N$81: IC14.6(B:-IN) LED5.2 R58.1
N$82: IC14.7(B:OUT) LED5.1
N$83: C46.2 IC13.1(A:OUT) IC13.5(B:+IN) R36.2
N$84: IC13.6(B:-IN) LED3.2 R56.1
N$85: IC13.7(B:OUT) LED3.1
N$86: J6.P3 R35.1 R41.1
N$87: C44.1 IC12.2(A:-IN) R41.2 R47.1
N$88: C45.1 IC12.13(D:-IN) R42.2 R50.1
N$89: J5.P3 R34.1 R42.1
N$90: C45.2 IC12.10(C:+IN) IC12.14(D:OUT) R34.2
N$91: IC12.9(C:-IN) LED6.2 R55.1
N$92: IC12.8(C:OUT) LED6.1
N$93: C44.2 IC12.1(A:OUT) IC12.5(B:+IN) R35.2
N$94: IC12.6(B:-IN) LED4.2 R54.1
N$95: IC12.7(B:OUT) LED4.1
VCC: C50.1 C52.1 C54.1 IC12.4(P:V+) IC13.4(P:V+) IC14.4(P:V+) ; also sheet 6
VEE: C51.2 C53.2 C55.2 IC12.11(P:V-) IC13.11(P:V-) IC14.11(P:V-) ; also sheet 6
VREF_BIAS: C43.1 IC12.3(A:+IN) IC12.12(D:+IN) IC13.3(A:+IN) IC13.12(D:+IN) IC14.3(A:+IN) IC14.12(D:+IN) R40.1 R48.2
Unconnected: IC4.8(VOUTH) IC4.9(VOUTF) J1.P2 J2.P2 J3.P2 J4.P2 J5.P2 J6.P2

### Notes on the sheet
- -8.1V to 8.1V | -8.1V to 8.1V
- -8.1V to 8.1V
- -8.1V to 8.1V | -8.1V to 8.1V | -8.1V to 8.1V
- 1.087V
- cc-by-sa | DAC&CV outputs
- Émilie Gillet
- emilie.o.gillet@gmail.com

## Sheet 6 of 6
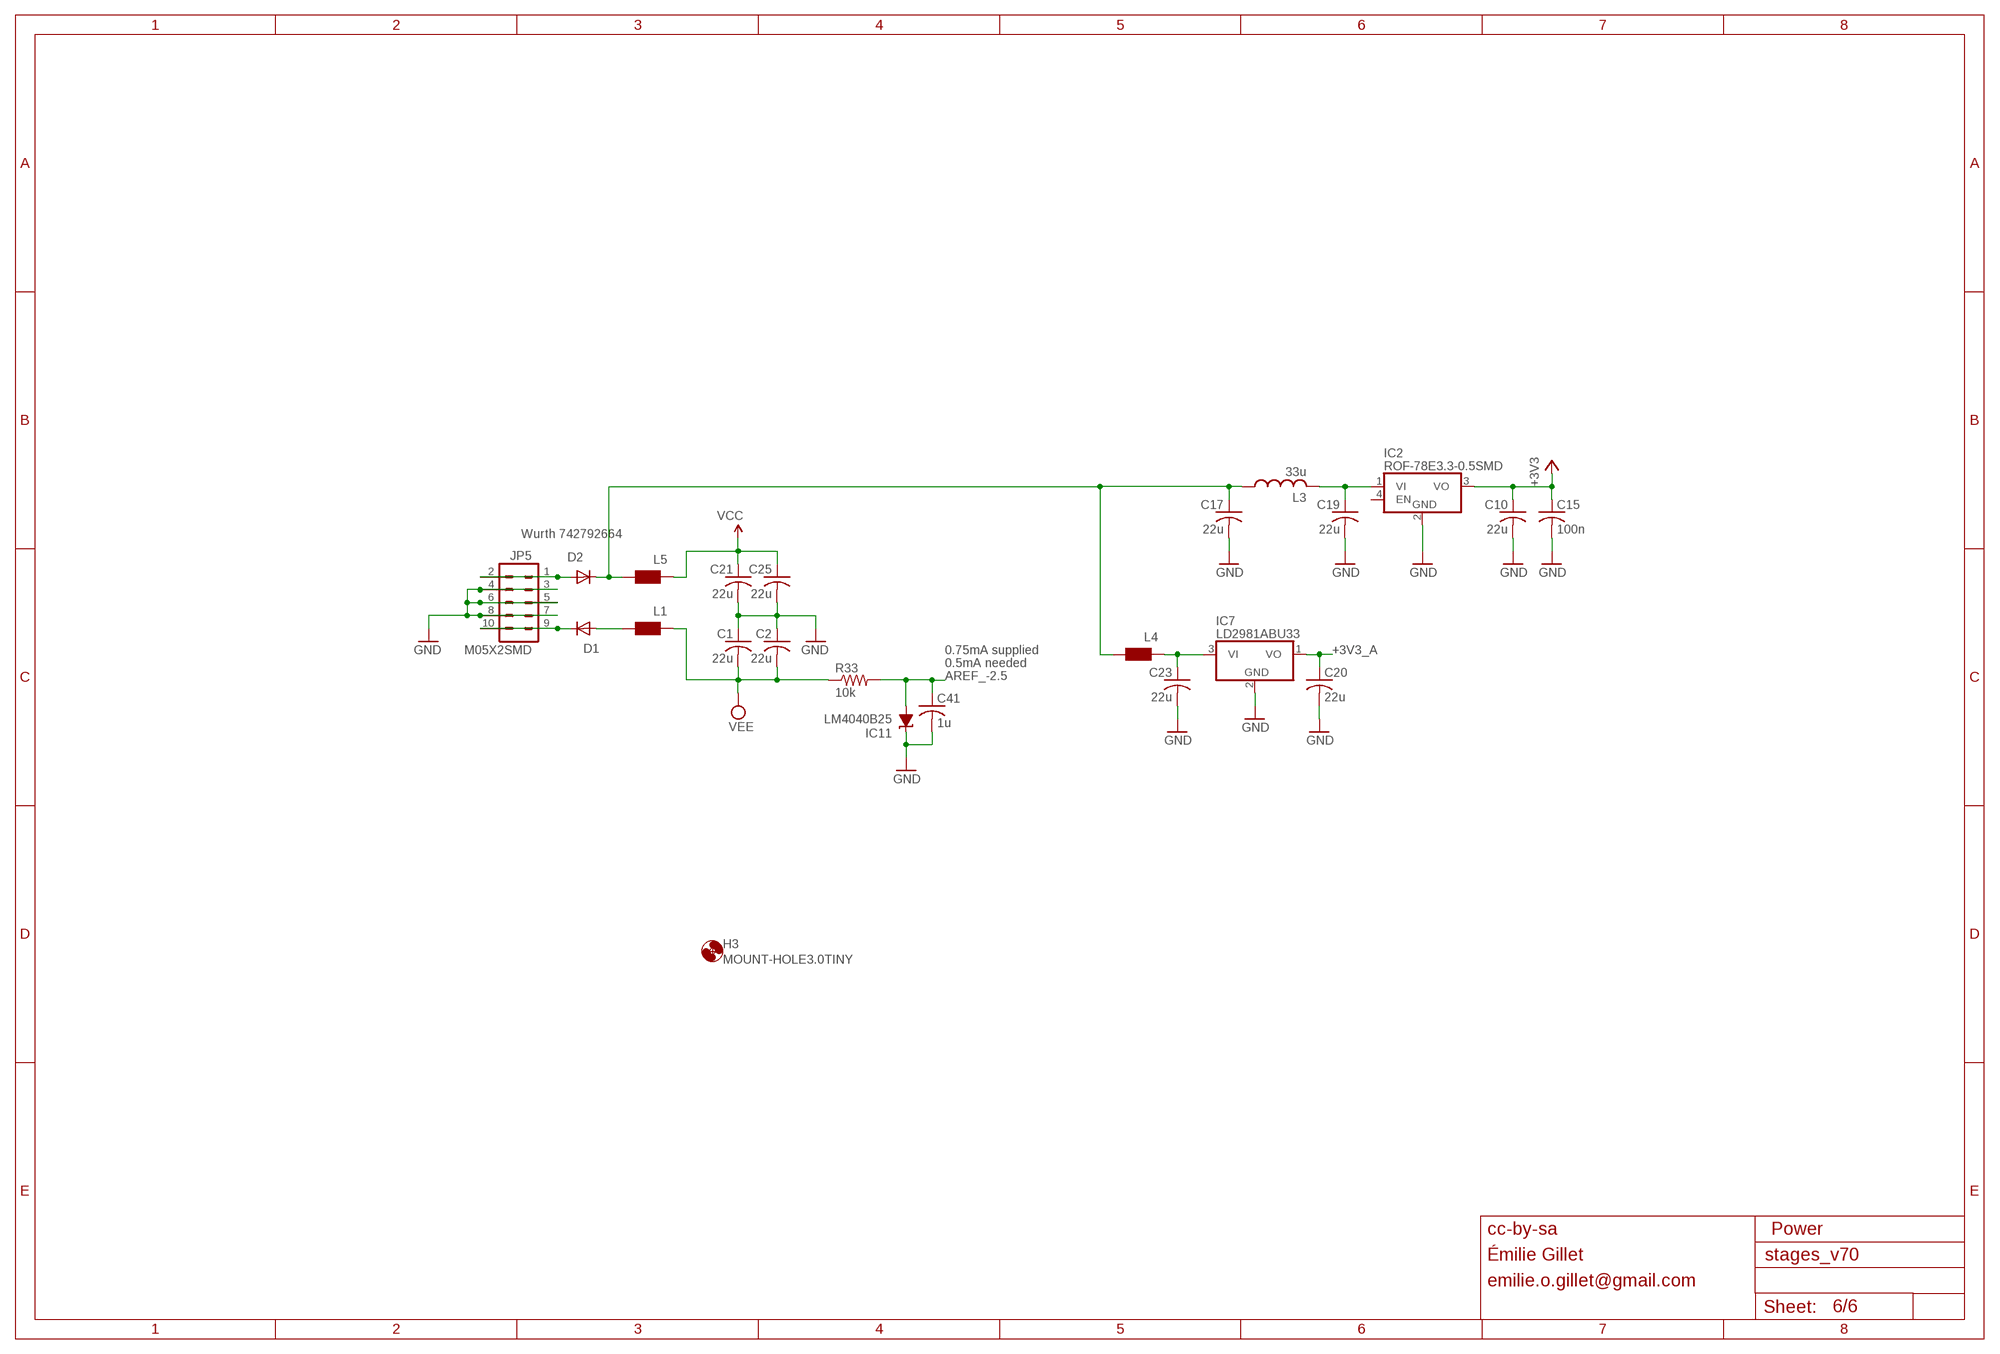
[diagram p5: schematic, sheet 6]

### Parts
C1  22u  C-USC1206  [C1206]
C2  22u  C-USC1206  [C1206]
C10  22u  C-USC1206  [C1206]
C15  100n  C-USC0402  [C0402]
C17  22u  C-USC1206  [C1206]
C19  22u  C-USC1206  [C1206]
C20  22u  C-USC1206  [C1206]
C21  22u  C-USC1206  [C1206]
C23  22u  C-USC1206  [C1206]
C25  22u  C-USC1206  [C1206]
C41  1u  C-USC0402  [C0402]
D1  1N5819HW  DIODE-SOD123  [SOD123]
D2  1N5819HW  DIODE-SOD123  [SOD123]
H3  MOUNT-HOLE3.0TINY  [3,0TINY]
IC2  ROF-78E3.3-0.5SMD  ROF-78EXX-0.55SMD  [ROF78EXX-0.5SMD]
IC7  LD2981ABU33  LD2981ABU  [SOT89]
IC11  LM4040B25  LM4041B12DBZ  [DBZ_R-PDSO-G3]
JP5  M05X2SMD  [2X5-SMD]
L1  WE-CBF_0603  [0603]
L3  33u  L-USL2012C  [L2012C]
L4  WE-CBF_0603  [0603]
L5  WE-CBF_0603  [0603]
R33  10k  R-US_R0402  [R0402]

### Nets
+3V3: C10.1 C15.1 IC2.3(VO) ; also sheet 1,2,4
+3V3_A: C20.1 IC7.1(VO) ; also sheet 1,2,3,5
AREF_-2.5: C41.1 IC11.2(A) R33.2 ; also sheet 3
GND: C1.1 C2.1 C10.2 C15.2 C17.2 C19.2 C20.2 C21.2 C23.2 C25.2 C41.2 IC2.2(GND) IC7.2(GND) IC11.1(C) JP5.3 JP5.4 JP5.5 JP5.6 JP5.7 JP5.8 ; also sheet 1,2,3,4,5
N$18: D2.A JP5.1 JP5.2
N$33: D1.A L1.2
N$35: C23.1 IC7.3(VI) L4.1
N$38: C17.1 D2.C L3.1 L4.2 L5.2
N$96: D1.C JP5.9 JP5.10
N$99: C19.1 IC2.1(VI) L3.2
VCC: C21.1 C25.1 L5.1 ; also sheet 5
VEE: C1.2 C2.2 L1.1 R33.1 ; also sheet 5
Unconnected: IC2.4(EN)

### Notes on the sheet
- Wurth 742792664
- 0.75mA supplied
- 0.5mA needed
- cc-by-sa | Power
- Émilie Gillet
- emilie.o.gillet@gmail.com

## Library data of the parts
C1-C55 = rcl:C-US: CAPACITOR, American symbol
D1-D8 = diode:DIODE-: DIODE
D9 = diode:DIODE_2CACA-: 2 Diodes - Cathode-Anode|Cathode-Anode
H1-H3 = og-holes:MOUNT-HOLE: MOUNTING HOLE with drill center marker
IC1 = og-ics:TLC59281
IC2 = og-vreg:ROF-78EXX-0.55SMD
IC3 IC6 = og-ics:4051: 8-channel ANALOG MULTIPLEXER
IC4 = og-dac:DAC8168
IC5 = og-stm32f2:STM32F373R
IC7 = og-vreg:LD2981
IC8-IC10 = og-linear:OPA1652
IC11 = texas:LM4041: PRECISION MICROPOWER SHUNT VOLTAGE REFERENCE
IC12-IC14 = linear:TL074: OP AMP
J1-J18 = og-pj301_variations:PJ301_THONKICONN
JP1 JP2 JP7 JP8 = SparkFun:FIDUCIAL: Fiducial Alignment Points
JP3 JP4 = SparkFun:M03: Header 3 Standard 3-pin 0.1" header. Use with straight break away headers (SKU : PRT-00116), right angle break away headers (PRT-00553), swiss pins (PRT-00743), machine pins (PRT-00117), and female headers (PRT-00115). Molex polarized connector foot print use with SKU : PRT-08232 with associated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
JP5 = og-header:M05X2: Header 5x2 Standard 10-pin dual row 0.1" header. Commonly used with AVR-ISP. Use with Spark Fun Electronics SKU: PRT-00778
JP6 = SparkFun:M04: Header 4 Standard 4-pin 0.1" header. Use with straight break away headers (SKU : PRT-00116), right angle break away headers (PRT-00553), swiss pins (PRT-00743), machine pins (PRT-00117), and female headers (PRT-00115). Molex polarized connector foot print use with SKU : PRT-08231 with associated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
L1 L2 L4 L5 = wuerth-elektronik:WE-CBF: SMD EMI Suppression Ferrite Beads
L3 = og-rcl:L-US
LED1-LED6 = og-leds:LED-BICOLOR-SHARED-THROUGHHOLE
LED7-LED12 = og-leds:LED-BICOLOR-THROUGHHOLE-CA
Q1 = og-crystal:CRYSTAL: Crystal with 2 extra terminals for the metal LID (Abracon ABMM2 for example)
Q2-Q7 = transistor:*-NPN-: NPN Transistror BF959 corrected 2008.03.06
R1-R77 = rcl:R-US_: RESISTOR, American symbol
R78-R83 = og-pots:BOURNS_SLIDER
R84-R89 = og-pots:POT_US
SW1-SW6 = SparkFun:TAC_SWITCH: Momentary Switch Button commonly used for reset or general input. Spark Fun Electronics SKU : COM-00097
